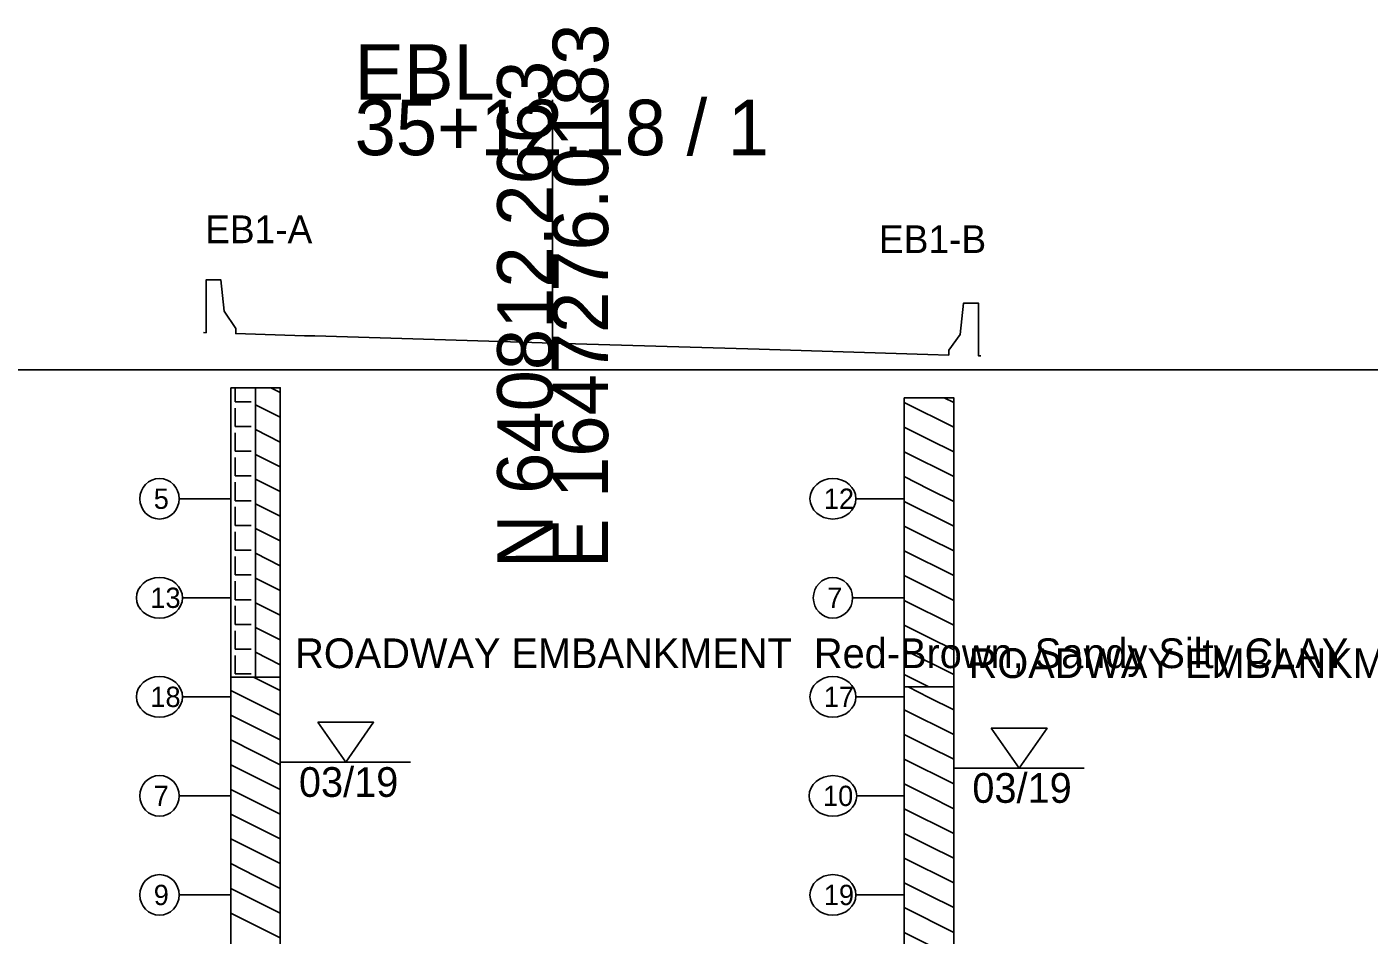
# Model space of a CAD drawing. Extents: x -26 to 303, y -74 to 518.
# Drawn here: x 123.5 to 191.2, y -28.5 to 17.3 of the extents above; entities that cross this region are included whole.
import ezdxf

# ---------------------------------------------------------------- set-up
doc = ezdxf.new("R2010")
doc.units = 0
for name, color, linetype in [('Exist Cross Section Cell', 7, 'Continuous'), ('Exist XS Ground Line', 7, 'Continuous'), ('Prop Road Sect_ Boring - Header Labels from Geopak', 7, 'Continuous'), ('Prop Road Sect_ Boring - Material (Desc Tx)', 7, 'Continuous'), ('Prop Road Sect_ Boring - Material (Outline)', 7, 'Continuous'), ('Prop Road Sect_ Boring - Peripheral (24 Hr GrdWtr Date)', 7, 'Continuous'), ('Prop Road Sect_ Boring - Peripheral (SPT Oval + Leader)', 7, 'Continuous'), ('Prop Road Sect_ Boring - Peripheral (SPT Tx)', 7, 'Continuous'), ('Water Mark (24 Hr) Cell', 7, 'Continuous')]:
    doc.layers.add(name, color=color, linetype=linetype)

msp = doc.modelspace()

# ---------------------------------------------------------------- linework, layer by layer
at = {"layer": 'Exist Cross Section Cell'}
for p, q in [((150, 0), (150, 13.641)), ((0, 0), (150, 0)), ((150, 0), (300, 0))]:
    msp.add_line(p, q, dxfattribs=at)
at = {"layer": 'Exist XS Ground Line'}
msp.add_lwpolyline([(132.375, 1.884), (132.5, 1.88), (132.501, 4.547), (133.251, 4.547), (133.418, 2.964), (133.999, 2.085), (134, 1.835), (137.473, 1.731), (138, 1.715), (148.419, 1.403), (150, 1.355), (150, 1.355), (150, 1.355), (160.419, 1.043), (162, 0.995), (168.946, 0.787), (170, 0.755), (170.001, 1.005), (170.582, 1.794), (170.749, 3.377), (171.499, 3.377), (171.5, 0.71), (171.625, 0.707)], dxfattribs=at)
msp.add_lwpolyline([(132.375, 1.884), (132.5, 1.88), (132.501, 4.547), (133.251, 4.547), (133.418, 2.964), (133.999, 2.085), (134, 1.835), (137.473, 1.731), (138, 1.715), (148.419, 1.403), (150, 1.355), (150, 1.355), (150, 1.355), (160.419, 1.043), (162, 0.995), (168.946, 0.787), (170, 0.755), (170.001, 1.005), (170.582, 1.794), (170.749, 3.377), (171.499, 3.377), (171.5, 0.71), (171.625, 0.707)], dxfattribs=at)
at = {"layer": 'Prop Road Sect_ Boring - Material (Outline)'}
for p, q in [((133.968, -0.9), (133.968, -1.605)), ((133.968, -0.9), (133.968, -1.605)), ((134.999, -0.9), (134.999, -3.012)), ((134.999, -0.9), (134.999, -3.012)), ((135.769, -0.9), (136.248, -1.139)), ((135.769, -0.9), (136.248, -1.139)), ((133.968, -1.605), (134.781, -1.605)), ((133.968, -1.605), (134.781, -1.605)), ((133.968, -1.922), (133.968, -2.854)), ((133.968, -1.922), (133.968, -2.854)), ((134.999, -1.764), (136.248, -2.388)), ((134.999, -1.764), (136.248, -2.388)), ((167.75, -1.639), (170.248, -2.888)), ((167.75, -1.639), (170.248, -2.888)), ((167.75, -1.639), (170.248, -2.888)), ((167.75, -1.639), (170.248, -2.888)), ((169.769, -1.4), (170.248, -1.639)), ((169.769, -1.4), (170.248, -1.639)), ((170.248, -1.639), (170.25, -1.641)), ((170.248, -1.639), (170.25, -1.641)), ((170.248, -1.639), (170.25, -1.641)), ((170.248, -1.639), (170.25, -1.641)), ((133.968, -2.854), (134.781, -2.854)), ((133.968, -2.854), (134.781, -2.854)), ((133.968, -3.171), (133.968, -4.103)), ((133.968, -3.171), (133.968, -4.103)), ((134.999, -3.012), (134.999, -5.51)), ((134.999, -3.012), (136.248, -3.637)), ((134.999, -3.012), (134.999, -5.51)), ((134.999, -3.012), (136.248, -3.637)), ((167.75, -2.888), (168.999, -3.512)), ((167.75, -2.888), (168.999, -3.512)), ((170.248, -2.888), (170.25, -2.889)), ((170.248, -2.888), (170.25, -2.889)), ((168.999, -3.512), (170.248, -4.137)), ((168.999, -3.512), (170.248, -4.137)), ((133.968, -4.103), (134.781, -4.103)), ((133.968, -4.103), (134.781, -4.103)), ((133.968, -4.42), (133.968, -5.351)), ((133.968, -4.42), (133.968, -5.351)), ((134.999, -4.261), (136.248, -4.886)), ((134.999, -4.261), (136.248, -4.886)), ((167.75, -4.137), (170.248, -5.386)), ((167.75, -4.137), (170.248, -5.386)), ((167.75, -4.137), (170.248, -5.386)), ((167.75, -4.137), (170.248, -5.386)), ((170.248, -4.137), (170.25, -4.138)), ((170.248, -4.137), (170.25, -4.138)), ((170.248, -4.137), (170.25, -4.138)), ((170.248, -4.137), (170.25, -4.138)), ((133.968, -5.351), (134.781, -5.351)), ((133.968, -5.351), (134.781, -5.351)), ((167.75, -5.386), (168.999, -6.01)), ((167.75, -5.386), (168.999, -6.01)), ((170.248, -5.386), (170.25, -5.387)), ((170.248, -5.386), (170.25, -5.387)), ((133.968, -5.669), (133.968, -6.6)), ((133.968, -5.669), (133.968, -6.6)), ((134.999, -5.51), (134.999, -8.007)), ((134.999, -5.51), (136.248, -6.134)), ((134.999, -5.51), (134.999, -8.007)), ((134.999, -5.51), (136.248, -6.134)), ((168.999, -6.01), (170.248, -6.634)), ((168.999, -6.01), (170.248, -6.634)), ((133.968, -6.6), (134.781, -6.6)), ((133.968, -6.6), (134.781, -6.6)), ((134.999, -6.759), (136.248, -7.383)), ((134.999, -6.759), (136.248, -7.383)), ((167.75, -6.634), (170.248, -7.883)), ((167.75, -6.634), (170.248, -7.883)), ((167.75, -6.634), (170.248, -7.883)), ((167.75, -6.634), (170.248, -7.883)), ((170.248, -6.634), (170.25, -6.636)), ((170.248, -6.634), (170.25, -6.636)), ((170.248, -6.634), (170.25, -6.636)), ((170.248, -6.634), (170.25, -6.636)), ((133.968, -6.917), (133.968, -7.849)), ((133.968, -6.917), (133.968, -7.849)), ((133.968, -7.849), (134.781, -7.849)), ((133.968, -7.849), (134.781, -7.849)), ((134.999, -8.007), (134.999, -10.505)), ((134.999, -8.007), (136.248, -8.632)), ((134.999, -8.007), (134.999, -10.505)), ((134.999, -8.007), (136.248, -8.632)), ((167.75, -7.883), (168.999, -8.507)), ((167.75, -7.883), (168.999, -8.507)), ((170.248, -7.883), (170.25, -7.884)), ((170.248, -7.883), (170.25, -7.884)), ((133.968, -8.166), (133.968, -9.098)), ((133.968, -8.166), (133.968, -9.098)), ((168.999, -8.507), (170.248, -9.132)), ((168.999, -8.507), (170.248, -9.132)), ((133.968, -9.098), (134.781, -9.098)), ((133.968, -9.098), (134.781, -9.098)), ((133.968, -9.415), (133.968, -10.346)), ((133.968, -9.415), (133.968, -10.346)), ((134.999, -9.256), (136.248, -9.881)), ((134.999, -9.256), (136.248, -9.881)), ((167.75, -9.132), (170.248, -10.381)), ((167.75, -9.132), (170.248, -10.381)), ((167.75, -9.132), (170.248, -10.381)), ((167.75, -9.132), (170.248, -10.381)), ((170.248, -9.132), (170.25, -9.133)), ((170.248, -9.132), (170.25, -9.133)), ((170.248, -9.132), (170.25, -9.133)), ((170.248, -9.132), (170.25, -9.133)), ((133.968, -10.346), (134.781, -10.346)), ((133.968, -10.346), (134.781, -10.346)), ((133.968, -10.664), (133.968, -11.595)), ((133.968, -10.664), (133.968, -11.595)), ((134.999, -10.505), (134.999, -13.002)), ((134.999, -10.505), (136.248, -11.129)), ((134.999, -10.505), (134.999, -13.002)), ((134.999, -10.505), (136.248, -11.129)), ((167.75, -10.381), (168.999, -11.005)), ((167.75, -10.381), (168.999, -11.005)), ((170.248, -10.381), (170.25, -10.382)), ((170.248, -10.381), (170.25, -10.382)), ((168.999, -11.005), (170.248, -11.629)), ((168.999, -11.005), (170.248, -11.629)), ((133.968, -11.595), (134.781, -11.595)), ((133.968, -11.595), (134.781, -11.595)), ((133.968, -11.912), (133.968, -12.844)), ((133.968, -11.912), (133.968, -12.844)), ((134.999, -11.754), (136.248, -12.378)), ((134.999, -11.754), (136.248, -12.378)), ((167.75, -11.629), (170.248, -12.878)), ((167.75, -11.629), (170.248, -12.878)), ((167.75, -11.629), (170.248, -12.878)), ((167.75, -11.629), (170.248, -12.878)), ((170.248, -11.629), (170.25, -11.631)), ((170.248, -11.629), (170.25, -11.631)), ((170.248, -11.629), (170.25, -11.631)), ((170.248, -11.629), (170.25, -11.631)), ((133.968, -12.844), (134.781, -12.844)), ((133.968, -12.844), (134.781, -12.844)), ((133.968, -13.161), (133.968, -14.093)), ((133.968, -13.161), (133.968, -14.093)), ((134.999, -13.002), (134.999, -15.5)), ((134.999, -13.002), (136.248, -13.627)), ((134.999, -13.002), (134.999, -15.5)), ((134.999, -13.002), (136.248, -13.627)), ((167.75, -12.878), (168.999, -13.502)), ((167.75, -12.878), (168.999, -13.502)), ((168.999, -13.502), (170.248, -14.127)), ((168.999, -13.502), (170.248, -14.127)), ((170.248, -12.878), (170.25, -12.879)), ((170.248, -12.878), (170.25, -12.879)), ((133.968, -14.093), (134.781, -14.093)), ((133.968, -14.093), (134.781, -14.093)), ((167.75, -14.127), (170.248, -15.376)), ((167.75, -14.127), (170.248, -15.376)), ((167.75, -14.127), (170.248, -15.376)), ((167.75, -14.127), (170.248, -15.376)), ((170.248, -14.127), (170.25, -14.128)), ((170.248, -14.127), (170.25, -14.128)), ((170.248, -14.127), (170.25, -14.128)), ((170.248, -14.127), (170.25, -14.128)), ((133.968, -14.41), (133.968, -15.341)), ((133.968, -14.41), (133.968, -15.341)), ((134.999, -14.251), (136.248, -14.876)), ((134.999, -14.251), (136.248, -14.876)), ((133.968, -15.341), (134.781, -15.341)), ((133.968, -15.341), (134.781, -15.341)), ((134.889, -15.5), (134.999, -15.555)), ((134.889, -15.5), (134.999, -15.555)), ((134.999, -15.555), (136.248, -16.179)), ((134.999, -15.555), (136.248, -16.179)), ((167.75, -15.376), (168.999, -16)), ((167.75, -15.376), (168.999, -16)), ((170.248, -15.376), (170.25, -15.377)), ((170.248, -15.376), (170.25, -15.377)), ((133.75, -16.179), (136.248, -17.428)), ((133.75, -16.179), (136.248, -17.428)), ((133.75, -16.179), (136.248, -17.428)), ((133.75, -16.179), (136.248, -17.428)), ((136.248, -16.179), (136.25, -16.181)), ((136.248, -16.179), (136.25, -16.181)), ((136.248, -16.179), (136.25, -16.181)), ((136.248, -16.179), (136.25, -16.181)), ((167.944, -16), (168.999, -16.527)), ((167.944, -16), (168.999, -16.527)), ((168.999, -16.527), (170.248, -17.152)), ((168.999, -16.527), (170.248, -17.152)), ((133.75, -17.428), (134.999, -18.052)), ((133.75, -17.428), (134.999, -18.052)), ((136.248, -17.428), (136.25, -17.429)), ((136.248, -17.428), (136.25, -17.429)), ((167.75, -17.152), (170.248, -18.401)), ((167.75, -17.152), (170.248, -18.401)), ((167.75, -17.152), (170.248, -18.401)), ((167.75, -17.152), (170.248, -18.401)), ((170.248, -17.152), (170.25, -17.153)), ((170.248, -17.152), (170.25, -17.153)), ((170.248, -17.152), (170.25, -17.153)), ((170.248, -17.152), (170.25, -17.153)), ((134.999, -18.052), (136.248, -18.677)), ((134.999, -18.052), (136.248, -18.677)), ((133.75, -18.677), (136.248, -19.926)), ((133.75, -18.677), (136.248, -19.926)), ((133.75, -18.677), (136.248, -19.926)), ((133.75, -18.677), (136.248, -19.926)), ((136.248, -18.677), (136.25, -18.678)), ((136.248, -18.677), (136.25, -18.678)), ((136.248, -18.677), (136.25, -18.678)), ((136.248, -18.677), (136.25, -18.678)), ((167.75, -18.401), (168.999, -19.025)), ((167.75, -18.401), (168.999, -19.025)), ((170.248, -18.401), (170.25, -18.402)), ((170.248, -18.401), (170.25, -18.402)), ((167.75, -19.649), (170.248, -20.898)), ((167.75, -19.649), (170.248, -20.898)), ((167.75, -19.649), (170.248, -20.898)), ((167.75, -19.649), (170.248, -20.898)), ((168.999, -19.025), (170.248, -19.649)), ((168.999, -19.025), (170.248, -19.649)), ((170.248, -19.649), (170.25, -19.651)), ((170.248, -19.649), (170.25, -19.651)), ((170.248, -19.649), (170.25, -19.651)), ((170.248, -19.649), (170.25, -19.651)), ((133.75, -19.926), (134.999, -20.55)), ((133.75, -19.926), (134.999, -20.55)), ((136.248, -19.926), (136.25, -19.927)), ((136.248, -19.926), (136.25, -19.927)), ((134.999, -20.55), (136.248, -21.174)), ((134.999, -20.55), (136.248, -21.174)), ((167.75, -20.898), (168.999, -21.522)), ((167.75, -20.898), (168.999, -21.522)), ((170.248, -20.898), (170.25, -20.899)), ((170.248, -20.898), (170.25, -20.899)), ((133.75, -21.174), (136.248, -22.423)), ((133.75, -21.174), (136.248, -22.423)), ((133.75, -21.174), (136.248, -22.423)), ((133.75, -21.174), (136.248, -22.423)), ((136.248, -21.174), (136.25, -21.176)), ((136.248, -21.174), (136.25, -21.176)), ((136.248, -21.174), (136.25, -21.176)), ((136.248, -21.174), (136.25, -21.176)), ((168.999, -21.522), (170.248, -22.147)), ((168.999, -21.522), (170.248, -22.147)), ((167.75, -22.147), (170.248, -23.396)), ((167.75, -22.147), (170.248, -23.396)), ((167.75, -22.147), (170.248, -23.396)), ((167.75, -22.147), (170.248, -23.396)), ((170.248, -22.147), (170.25, -22.148)), ((170.248, -22.147), (170.25, -22.148)), ((170.248, -22.147), (170.25, -22.148)), ((170.248, -22.147), (170.25, -22.148)), ((133.75, -22.423), (134.999, -23.047)), ((133.75, -22.423), (134.999, -23.047)), ((136.248, -22.423), (136.25, -22.424)), ((136.248, -22.423), (136.25, -22.424)), ((133.75, -23.672), (136.248, -24.921)), ((133.75, -23.672), (136.248, -24.921)), ((133.75, -23.672), (136.248, -24.921)), ((133.75, -23.672), (136.248, -24.921)), ((134.999, -23.047), (136.248, -23.672)), ((134.999, -23.047), (136.248, -23.672)), ((136.248, -23.672), (136.25, -23.673)), ((136.248, -23.672), (136.25, -23.673)), ((136.248, -23.672), (136.25, -23.673)), ((136.248, -23.672), (136.25, -23.673)), ((167.75, -23.396), (168.999, -24.02)), ((167.75, -23.396), (168.999, -24.02)), ((170.248, -23.396), (170.25, -23.397)), ((170.248, -23.396), (170.25, -23.397)), ((168.999, -24.02), (170.248, -24.644)), ((168.999, -24.02), (170.248, -24.644)), ((133.75, -24.921), (134.999, -25.545)), ((133.75, -24.921), (134.999, -25.545)), ((136.248, -24.921), (136.25, -24.922)), ((136.248, -24.921), (136.25, -24.922)), ((167.75, -24.644), (170.248, -25.893)), ((167.75, -24.644), (170.248, -25.893)), ((167.75, -24.644), (170.248, -25.893)), ((167.75, -24.644), (170.248, -25.893)), ((170.248, -24.644), (170.25, -24.646)), ((170.248, -24.644), (170.25, -24.646)), ((170.248, -24.644), (170.25, -24.646)), ((170.248, -24.644), (170.25, -24.646)), ((134.999, -25.545), (136.248, -26.169)), ((134.999, -25.545), (136.248, -26.169)), ((133.75, -26.169), (136.248, -27.418)), ((133.75, -26.169), (136.248, -27.418)), ((133.75, -26.169), (136.248, -27.418)), ((133.75, -26.169), (136.248, -27.418)), ((136.248, -26.169), (136.25, -26.171)), ((136.248, -26.169), (136.25, -26.171)), ((136.248, -26.169), (136.25, -26.171)), ((136.248, -26.169), (136.25, -26.171)), ((167.75, -25.893), (168.999, -26.517)), ((167.75, -25.893), (168.999, -26.517)), ((170.248, -25.893), (170.25, -25.894)), ((170.248, -25.893), (170.25, -25.894)), ((168.999, -26.517), (170.248, -27.142)), ((168.999, -26.517), (170.248, -27.142)), ((133.75, -27.418), (134.999, -28.042)), ((133.75, -27.418), (134.999, -28.042)), ((136.248, -27.418), (136.25, -27.419)), ((136.248, -27.418), (136.25, -27.419)), ((167.75, -27.142), (170.248, -28.391)), ((167.75, -27.142), (170.248, -28.391)), ((167.75, -27.142), (170.248, -28.391)), ((167.75, -27.142), (170.248, -28.391)), ((170.248, -27.142), (170.25, -27.143)), ((170.248, -27.142), (170.25, -27.143)), ((170.248, -27.142), (170.25, -27.143)), ((170.248, -27.142), (170.25, -27.143)), ((134.999, -28.042), (136.248, -28.667)), ((134.999, -28.042), (136.248, -28.667)), ((167.75, -28.391), (168.999, -29.015)), ((167.75, -28.391), (168.999, -29.015)), ((170.248, -28.391), (170.25, -28.392)), ((170.248, -28.391), (170.25, -28.392))]:
    msp.add_line(p, q, dxfattribs=at)
for points in [[(133.75, -0.9), (136.25, -0.9), (136.25, -15.5), (133.75, -15.5)], [(167.75, -1.4), (170.25, -1.4), (170.25, -16), (167.75, -16)], [(133.75, -15.5), (136.25, -15.5), (136.25, -70.5), (133.75, -70.5)], [(167.75, -16), (170.25, -16), (170.25, -44), (167.75, -44)]]:
    msp.add_lwpolyline(points, close=True, dxfattribs=at)
at = {"layer": 'Prop Road Sect_ Boring - Peripheral (SPT Oval + Leader)'}
for p, q in [((133.75, -6.5), (131.141, -6.5)), ((167.75, -6.5), (165.31, -6.5)), ((133.75, -11.5), (131.31, -11.5)), ((167.75, -11.5), (165.141, -11.5)), ((133.75, -16.5), (131.31, -16.5)), ((167.75, -16.5), (165.31, -16.5)), ((133.75, -21.5), (131.141, -21.5)), ((167.75, -21.5), (165.35, -21.5)), ((133.75, -26.5), (131.141, -26.5)), ((167.75, -26.5), (165.31, -26.5))]:
    msp.add_line(p, q, dxfattribs=at)
for centre, major_axis, ratio in [((130.15, -6.5), (0, 1.025), 0.966391), ((164.15, -6.5), (1.16, 0), 0.883591), ((130.15, -11.5), (1.16, 0), 0.883591), ((164.15, -11.5), (0, 1.025), 0.966391), ((130.15, -16.5), (1.16, 0), 0.883591), ((164.15, -16.5), (1.16, 0), 0.883591), ((130.15, -21.5), (0, 1.025), 0.966391), ((164.15, -21.5), (1.2, 0), 0.853887), ((130.15, -26.5), (0, 1.025), 0.966391), ((164.15, -26.5), (1.16, 0), 0.883591)]:
    msp.add_ellipse(centre, major_axis=major_axis, ratio=ratio, dxfattribs=at)
at = {"layer": 'Water Mark (24 Hr) Cell'}
for p, q in [((136.269, -19.8), (139.55, -19.8)), ((139.55, -19.8), (142.831, -19.8)), ((170.269, -20.1), (173.55, -20.1)), ((173.55, -20.1), (176.831, -20.1))]:
    msp.add_line(p, q, dxfattribs=at)
for points in [[(138.139, -17.782), (140.961, -17.782), (139.55, -19.8)], [(172.139, -18.082), (174.961, -18.082), (173.55, -20.1)]]:
    msp.add_lwpolyline(points, close=True, dxfattribs=at)

# ---------------------------------------------------------------- texts
at = {"layer": 'Exist Cross Section Cell'}
for s, p in [('E 1647276.0183', (152.8, -10)), ('N 640812.2663', (150, -10))]:
    msp.add_text(s, height=2.8, rotation=90, dxfattribs=at).set_placement(p)
for s, p in [('EBL', (140, 13.641)), ('35+12.18 / 1', (140, 10.841))]:
    msp.add_text(s, height=2.8, dxfattribs=at).set_placement(p)
at = {"layer": 'Prop Road Sect_ Boring - Header Labels from Geopak'}
for s, p in [('EB1-A', (132.454, 6.4)), ('EB1-B', (166.476, 5.9))]:
    msp.add_text(s, height=1.4, dxfattribs=at).set_placement(p)
at = {"layer": 'Prop Road Sect_ Boring - Material (Desc Tx)'}
for s, p in [('ROADWAY EMBANKMENT  Red-Brown, Sandy Silty CLAY', (137, -15.05)), ('ROADWAY EMBANKMENT  Red-Orange-Brown, Sandy Silty CLAY', (171, -15.55))]:
    msp.add_text(s, height=1.5, dxfattribs=at).set_placement(p)
at = {"layer": 'Prop Road Sect_ Boring - Peripheral (24 Hr GrdWtr Date)'}
for p in [(137.189, -21.55), (171.189, -21.85)]:
    msp.add_text('03/19', height=1.5, dxfattribs=at).set_placement(p)
at = {"layer": 'Prop Road Sect_ Boring - Peripheral (SPT Tx)'}
for s, p in [('5', (129.859, -7.012)), ('12', (163.69, -7.012)), ('13', (129.69, -12.012)), ('7', (163.859, -12.012)), ('18', (129.69, -17.012)), ('17', (163.69, -17.012)), ('7', (129.859, -22.012)), ('10', (163.65, -22.012)), ('9', (129.859, -27.012)), ('19', (163.69, -27.012))]:
    msp.add_text(s, height=1.025, dxfattribs=at).set_placement(p)

doc.saveas('drawing.dxf')
